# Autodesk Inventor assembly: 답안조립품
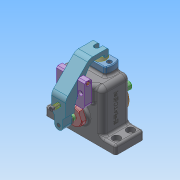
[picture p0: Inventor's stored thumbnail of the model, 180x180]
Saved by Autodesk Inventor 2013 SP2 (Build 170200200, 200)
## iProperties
Created: 2023-12
Part Number: 답안조립품
Document SubType Name: Assembly
Designer: i
Author: i
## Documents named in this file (14)
- C:\Users\i\Desktop\731208V1018\답안조립품.iam
- C:\Users\i\Desktop\731208V1018\답안본체부품.ipt
- C:\Users\i\Desktop\731208V1018\가공품.ipt
- C:\Users\i\Desktop\731208V1018\가이드 부시.ipt
- C:\Users\i\Desktop\731208V1018\고정대.ipt
- C:\Users\i\Desktop\731208V1018\브라켓.ipt
- C:\Users\i\Desktop\731208V1018\스프링.ipt
- C:\Users\i\Desktop\731208V1018\육각 머리 볼트 M6 x 12.ipt
- C:\Users\i\Desktop\731208V1018\육각 소켓 머리 볼트 M3 x 8.ipt
- C:\Users\i\Desktop\731208V1018\육각 소켓 머리 볼트 M3 x 30.ipt
- C:\Users\i\Desktop\731208V1018\조절 부시.ipt
- C:\Users\i\Desktop\731208V1018\클램프 샤프트.ipt
- C:\Users\i\Desktop\731208V1018\클램프.ipt
- C:\Users\i\Desktop\731208V1018\핀.ipt
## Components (4 placed, 4 different names)
1. 가공품:1
2. 가이드 부시:1
3. 고정대:1
4. 핀:1 — 플러쉬:1
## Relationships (1: Flush 1)
- 플러쉬:1 [Flush]: 핀:1
